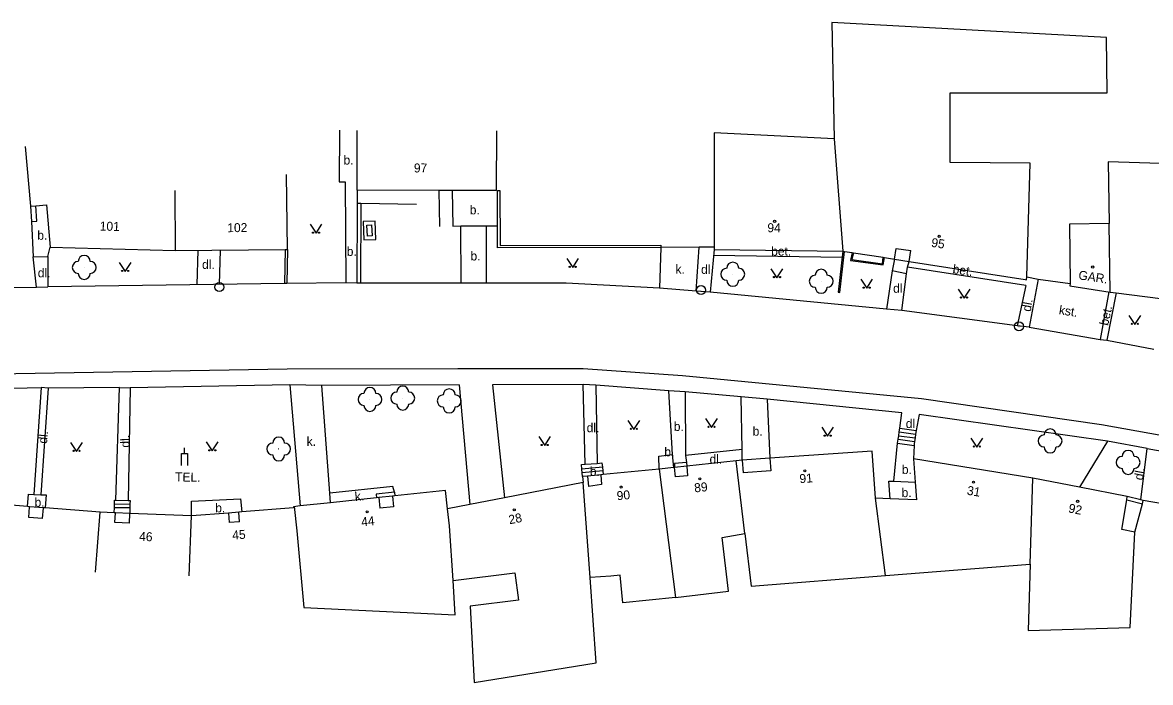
# Model space of a CAD drawing. Extents: x -582162 to -561283, y -1187583 to -1183539.
# Drawn here: x -571002.1 to -570907.8, y -1184952.9 to -1184897.8 of the extents above; entities that cross this region are included whole.
import ezdxf

# ---------------------------------------------------------------- set-up
doc = ezdxf.new("R2010")
doc.units = 0
for name, color, linetype in [('Vrstva 1', 7, 'Continuous'), ('Vrstva 10', 7, 'Continuous'), ('Vrstva 11', 7, 'Continuous'), ('Vrstva 14', 7, 'Continuous'), ('Vrstva 3', 7, 'Continuous'), ('Vrstva 4', 7, 'Continuous'), ('Vrstva 5', 7, 'Continuous'), ('Vrstva 6', 7, 'Continuous'), ('Vrstva 8', 7, 'Continuous'), ('Vrstva 9', 7, 'Continuous')]:
    doc.layers.add(name, color=color, linetype=linetype)

# ---------------------------------------------------------------- blocks, each defined once
blk = doc.blocks.new('1.079')
at = {"layer": 'Vrstva 1'}
for radius in [0.75, 0.001]:
    blk.add_circle((0, -0.001), radius, dxfattribs=at)
blk = doc.blocks.new('3.130')
at = {"layer": 'Vrstva 1'}
blk.add_circle((0, 0), 0.001, dxfattribs=at)
for centre, start, end in [((0, 1), 0, 180), ((-1, 0), 90, 270), ((1, 0), 270, 90), ((0, -1), 180, 360)]:
    blk.add_arc(centre, 1, start, end, dxfattribs=at)
blk = doc.blocks.new('3.140')
at = {"layer": 'Vrstva 1'}
blk.add_lwpolyline([(-1, 1.5), (0, 0), (1, 1.5)], dxfattribs=at)
for centre in [(-0.5, 0.1), (0.5, 0.1)]:
    blk.add_circle(centre, 0.1, dxfattribs=at)
blk = doc.blocks.new('4.020')
at = {"layer": 'Vrstva 1'}
blk.add_circle((0, 0), 0.175, dxfattribs=at)
blk = doc.blocks.new('4.120')
at = {"layer": 'Vrstva 1'}
blk.add_line((0, 2), (0, 3), dxfattribs=at)
blk.add_lwpolyline([(-0.5, 0), (-0.5, 2), (0.5, 2), (0.5, 0)], dxfattribs=at)

msp = doc.modelspace()

# ---------------------------------------------------------------- linework, layer by layer
at = {"layer": 'Vrstva 10'}
for points in [[(-570975.62, -1184906.76), (-570975.64, -1184911.07), (-570975.14, -1184911.07), (-570975.09, -1184919.5)], [(-570967.31, -1184911.79), (-570967.25, -1184914.79)], [(-570966.21, -1184911.79), (-570966.15, -1184914.77), (-570965.47, -1184914.73)], [(-570974.14, -1184912.84), (-570973.84, -1184912.84)], [(-570973.84, -1184912.84), (-570969.19, -1184912.92)], [(-571001.35, -1184914.38), (-571001.23, -1184917.32)], [(-570973.57, -1184915.91), (-570972.57, -1184915.87), (-570972.64, -1184914.35), (-570973.64, -1184914.39), (-570973.57, -1184915.91)], [(-570973.28, -1184915.6), (-570973.33, -1184914.67), (-570972.93, -1184914.66), (-570972.88, -1184915.58), (-570973.28, -1184915.6)], [(-570965.47, -1184914.73), (-570963.32, -1184914.75)], [(-570965.46, -1184919.53), (-570965.47, -1184914.73)], [(-570963.32, -1184914.75), (-570962.41, -1184914.74)], [(-570963.32, -1184919.53), (-570963.32, -1184914.75)], [(-570999.98, -1184917.3), (-570999.8, -1184916.52)], [(-570948.76, -1184916.56), (-570948.88, -1184919.95)], [(-570945.82, -1184920.19), (-570945.56, -1184916.53)], [(-571001.23, -1184917.32), (-570999.98, -1184917.3)], [(-571000.94, -1184919.85), (-571001.23, -1184917.32)], [(-570999.98, -1184917.3), (-570999.98, -1184919.84)], [(-570987.46, -1184916.78), (-570987.54, -1184919.67)], [(-570985.6, -1184916.77), (-570985.68, -1184919.65)], [(-570944.31, -1184916.72), (-570944.63, -1184920.29)], [(-570933.62, -1184917.38), (-570944.35, -1184917.21)], [(-570929.23, -1184917.52), (-570929.43, -1184918.5)], [(-570929.43, -1184918.5), (-570929.91, -1184921.69)], [(-570928.23, -1184918.74), (-570929.43, -1184918.5)], [(-570928.23, -1184918.74), (-570928.14, -1184918.19)], [(-570928.14, -1184918.19), (-570928.02, -1184917.71)], [(-570918.27, -1184919.73), (-570928.14, -1184918.19)], [(-570928.62, -1184921.81), (-570928.23, -1184918.74)], [(-570917.22, -1184919.2), (-570917.98, -1184923.19)], [(-571018.47, -1184919.98), (-571000.94, -1184919.85)], [(-571000.94, -1184919.85), (-570999.98, -1184919.84)], [(-570980.22, -1184919.57), (-570999.98, -1184919.84)], [(-570980.02, -1184919.57), (-570980.22, -1184919.57)], [(-570975.09, -1184919.5), (-570980.02, -1184919.57)], [(-570974.16, -1184919.54), (-570975.09, -1184919.5)], [(-570973.86, -1184919.54), (-570974.16, -1184919.54)], [(-570965.46, -1184919.53), (-570973.86, -1184919.54)], [(-570963.32, -1184919.53), (-570965.46, -1184919.53)], [(-570948.88, -1184919.95), (-570956.68, -1184919.53), (-570963.32, -1184919.53)], [(-570945.82, -1184920.19), (-570948.88, -1184919.95)], [(-570944.63, -1184920.29), (-570945.82, -1184920.19)], [(-570929.91, -1184921.69), (-570944.63, -1184920.29)], [(-570918.27, -1184919.73), (-570918.98, -1184923.08)], [(-570911.31, -1184920.25), (-570912.06, -1184924.23)], [(-570910.71, -1184920.34), (-570911.48, -1184924.29)], [(-570928.62, -1184921.81), (-570929.91, -1184921.69)], [(-570918.98, -1184923.08), (-570928.62, -1184921.81)], [(-570917.98, -1184923.19), (-570918.98, -1184923.08)], [(-570917.98, -1184923.19), (-570912.06, -1184924.23)], [(-570912.06, -1184924.23), (-570911.48, -1184924.29)], [(-570911.48, -1184924.29), (-570907.56, -1184925.03)], [(-571004.32, -1184927.09), (-570979.98, -1184926.69), (-570965.74, -1184926.67)], [(-570965.74, -1184926.67), (-570962.98, -1184926.67)], [(-570962.98, -1184926.67), (-570955.25, -1184926.66), (-570946.96, -1184927.24), (-570926.98, -1184929.16), (-570911.93, -1184931.33), (-570890.18, -1184935.24), (-570870.81, -1184939.01), (-570871.39, -1184940.27)], [(-571012.32, -1184928.52), (-571000.54, -1184928.25)], [(-571000.54, -1184928.25), (-571001.16, -1184937.17)], [(-570999.95, -1184928.29), (-571000.57, -1184937.2)], [(-570999.95, -1184928.29), (-571000.54, -1184928.25)], [(-570994.01, -1184928.24), (-570999.95, -1184928.29)], [(-570994.31, -1184937.66), (-570994.01, -1184928.24)], [(-570994.01, -1184928.24), (-570993.12, -1184928.27)], [(-570993.12, -1184928.27), (-570993.27, -1184937.68)], [(-570979.76, -1184928.03), (-570993.12, -1184928.27)], [(-570979.76, -1184928.03), (-570978.91, -1184938.14)], [(-570977.09, -1184928.07), (-570979.76, -1184928.03)], [(-570965.62, -1184928.03), (-570977.09, -1184928.07)], [(-570976.43, -1184937.06), (-570977.09, -1184928.07)], [(-570965.62, -1184928.03), (-570964.73, -1184938.01)], [(-570955.25, -1184928), (-570962.84, -1184928.02)], [(-570962.84, -1184928.02), (-570961.84, -1184937.46)], [(-570955.09, -1184934.65), (-570955.25, -1184928)], [(-570954.2, -1184928.06), (-570955.25, -1184928)], [(-570948.09, -1184928.51), (-570954.2, -1184928.06)], [(-570954.2, -1184928.06), (-570954.09, -1184934.58)], [(-570947.79, -1184933.84), (-570948.09, -1184928.51)], [(-570946.73, -1184928.61), (-570948.09, -1184928.51)], [(-570942.04, -1184929.01), (-570946.73, -1184928.61)], [(-570946.73, -1184928.61), (-570946.69, -1184933.92)], [(-570941.97, -1184933.42), (-570942.04, -1184929.01)], [(-570939.87, -1184929.22), (-570942.04, -1184929.01)], [(-570928.8, -1184931.65), (-570928.63, -1184930.35), (-570939.87, -1184929.22)], [(-570939.87, -1184929.22), (-570939.64, -1184934.16)], [(-570911.44, -1184932.74), (-570927.18, -1184930.5), (-570927.43, -1184931.84)], [(-570928.84, -1184931.96), (-570928.8, -1184931.65)], [(-570928.8, -1184931.65), (-570927.43, -1184931.84)], [(-570928.97, -1184932.89), (-570928.92, -1184932.57)], [(-570928.92, -1184932.57), (-570928.88, -1184932.27)], [(-570928.92, -1184932.57), (-570927.56, -1184932.76)], [(-570928.88, -1184932.27), (-570928.84, -1184931.96)], [(-570928.88, -1184932.27), (-570927.52, -1184932.45)], [(-570928.84, -1184931.96), (-570927.47, -1184932.14)], [(-570927.52, -1184932.45), (-570927.56, -1184932.76)], [(-570927.47, -1184932.14), (-570927.52, -1184932.45)], [(-570927.43, -1184931.84), (-570927.47, -1184932.14)], [(-570941.97, -1184933.42), (-570946.69, -1184933.92)], [(-570941.96, -1184934.32), (-570941.97, -1184933.42)], [(-570929.29, -1184936.08), (-570928.97, -1184932.89)], [(-570928.97, -1184932.89), (-570927.6, -1184933.08)], [(-570927.6, -1184933.08), (-570927.65, -1184934.19)], [(-570927.56, -1184932.76), (-570927.59, -1184932.94), (-570927.6, -1184933.08)], [(-570911.44, -1184932.74), (-570913.78, -1184936.57)], [(-570908.13, -1184933.33), (-570911.44, -1184932.74)], [(-570908.64, -1184937.63), (-570908.13, -1184933.33)], [(-570908.13, -1184933.33), (-570890.36, -1184936.5)], [(-570948.91, -1184935.06), (-570948.92, -1184933.97), (-570947.79, -1184933.84)], [(-570947.67, -1184934.93), (-570947.79, -1184933.84)], [(-570946.62, -1184934.5), (-570947.63, -1184934.6), (-570947.61, -1184934.92)], [(-570946.69, -1184933.92), (-570946.62, -1184934.5)], [(-570946.62, -1184934.5), (-570946.59, -1184934.81)], [(-570955.36, -1184935.06), (-570955.39, -1184934.67), (-570955.09, -1184934.65)], [(-570953.65, -1184934.89), (-570955.36, -1184935.06)], [(-570955.33, -1184935.37), (-570955.36, -1184935.06)], [(-570953.62, -1184935.21), (-570955.33, -1184935.37)], [(-570955.3, -1184935.69), (-570955.33, -1184935.37)], [(-570955.09, -1184934.65), (-570954.09, -1184934.58)], [(-570954.09, -1184934.58), (-570953.69, -1184934.55), (-570953.65, -1184934.89)], [(-570953.65, -1184934.89), (-570953.62, -1184935.21)], [(-570953.62, -1184935.21), (-570953.59, -1184935.52)], [(-570929.61, -1184937.55), (-570929.72, -1184936.06), (-570929.29, -1184936.08)], [(-570929.29, -1184936.08), (-570927.51, -1184936.15)], [(-571001.68, -1184938.19), (-571001.6, -1184937.14), (-571001.16, -1184937.17)], [(-571001.16, -1184937.17), (-571000.57, -1184937.2)], [(-571000.57, -1184937.2), (-571000.13, -1184937.22), (-571000.22, -1184938.3)], [(-570971.03, -1184937), (-570971.15, -1184936.5), (-570976.43, -1184937.06)], [(-570976.37, -1184937.87), (-570976.43, -1184937.06)], [(-570971.03, -1184937), (-570972.56, -1184937.16), (-570972.53, -1184937.46)], [(-570971.03, -1184937), (-570971, -1184937.3)], [(-570908.64, -1184937.63), (-570909.78, -1184937.34)], [(-570994.45, -1184938.72), (-570994.43, -1184938.26)], [(-570994.43, -1184938.26), (-570994.42, -1184937.96)], [(-570994.43, -1184938.26), (-570993.13, -1184938.28)], [(-570994.42, -1184937.96), (-570994.41, -1184937.66), (-570994.31, -1184937.66)], [(-570994.42, -1184937.96), (-570993.13, -1184937.98)], [(-570994.31, -1184937.66), (-570993.27, -1184937.68)], [(-570993.27, -1184937.68), (-570993.12, -1184937.68), (-570993.13, -1184937.98)], [(-570993.13, -1184938.28), (-570993.14, -1184938.77)], [(-570993.13, -1184937.98), (-570993.13, -1184938.28)], [(-570987.98, -1184938.97), (-570987.98, -1184937.73), (-570983.88, -1184937.54), (-570983.79, -1184938.64)], [(-570909.83, -1184937.64), (-570908.52, -1184937.97)], [(-570908.44, -1184937.68), (-570908.64, -1184937.63)]]:
    msp.add_lwpolyline(points, dxfattribs=at)
at = {"layer": 'Vrstva 4'}
for points in [[(-570974.15, -1184911.77), (-570974.14, -1184906.77)], [(-570962.5, -1184906.8), (-570962.52, -1184911.8), (-570966.21, -1184911.79)], [(-571001.88, -1184908.12), (-571001.44, -1184913.1)], [(-570979.97, -1184916.73), (-570980.04, -1184910.44)], [(-570989.37, -1184911.8), (-570989.34, -1184916.8)], [(-570967.31, -1184911.79), (-570974.15, -1184911.77)], [(-570966.21, -1184911.79), (-570967.31, -1184911.79)], [(-571001.44, -1184913.1), (-571000.99, -1184913.06)], [(-571000.99, -1184913.06), (-571000.09, -1184912.98), (-570999.8, -1184916.52)], [(-570999.8, -1184916.52), (-570989.34, -1184916.8)], [(-570944.31, -1184916.52), (-570944.31, -1184916.72)], [(-570929.23, -1184917.52), (-570929.1, -1184916.62)], [(-570989.34, -1184916.8), (-570980.17, -1184916.73)], [(-570980.17, -1184916.73), (-570979.97, -1184916.73)], [(-570944.31, -1184916.72), (-570933.56, -1184916.85)], [(-570933.56, -1184916.85), (-570933.41, -1184916.87)], [(-570933.41, -1184916.87), (-570932.77, -1184916.97)], [(-570932.77, -1184916.97), (-570932.67, -1184916.99)], [(-570932.67, -1184916.99), (-570930.17, -1184917.37)], [(-570930.17, -1184917.37), (-570930.07, -1184917.39)], [(-570930.07, -1184917.39), (-570929.23, -1184917.52)], [(-570929.23, -1184917.52), (-570928.02, -1184917.71)], [(-570928.02, -1184917.71), (-570927.88, -1184916.8)], [(-570928.02, -1184917.71), (-570918.31, -1184919.23)], [(-570918.31, -1184919.23), (-570918.21, -1184919.25)], [(-570918.21, -1184919.25), (-570918.17, -1184918.99)], [(-570914.56, -1184919.56), (-570914.59, -1184919.76)], [(-570914.59, -1184919.76), (-570914.04, -1184919.84)], [(-570914.04, -1184919.84), (-570911.74, -1184920.19)], [(-570911.74, -1184920.19), (-570911.2, -1184920.27)], [(-570911.2, -1184920.27), (-570910.71, -1184920.34)], [(-570910.71, -1184920.34), (-570907.01, -1184920.8), (-570905.97, -1184920.94), (-570898.31, -1184921.91)], [(-570930.81, -1184937.5), (-570931.09, -1184933.55), (-570939.64, -1184934.16)], [(-570942.46, -1184934.36), (-570946.59, -1184934.81)], [(-570941.96, -1184934.32), (-570942.46, -1184934.36)], [(-570939.64, -1184934.16), (-570941.96, -1184934.32)], [(-570941.96, -1184934.32), (-570941.88, -1184935.37)], [(-570939.64, -1184934.16), (-570939.56, -1184935.2)], [(-570927.65, -1184934.19), (-570927.51, -1184936.15)], [(-570917.68, -1184935.81), (-570927.65, -1184934.19)], [(-570948.91, -1184935.06), (-570953.59, -1184935.52)], [(-570947.67, -1184934.93), (-570948.91, -1184935.06)], [(-570947.61, -1184934.92), (-570947.67, -1184934.93)], [(-570946.59, -1184934.81), (-570947.61, -1184934.92)], [(-570947.54, -1184935.7), (-570947.61, -1184934.92)], [(-570946.59, -1184934.81), (-570946.52, -1184935.61)], [(-570955.25, -1184936.19), (-570961.84, -1184937.46)], [(-570954.89, -1184935.65), (-570955.3, -1184935.69)], [(-570955.3, -1184935.69), (-570955.25, -1184936.19)], [(-570953.79, -1184935.54), (-570954.89, -1184935.65)], [(-570954.89, -1184935.65), (-570954.81, -1184936.5)], [(-570953.59, -1184935.52), (-570953.79, -1184935.54)], [(-570953.79, -1184935.54), (-570953.71, -1184936.36)], [(-570927.51, -1184936.15), (-570927.4, -1184937.64), (-570929.61, -1184937.55)], [(-570913.78, -1184936.57), (-570917.68, -1184935.81)], [(-570971.2, -1184937.32), (-570972.33, -1184937.44)], [(-570971, -1184937.3), (-570971.2, -1184937.32)], [(-570971.2, -1184937.32), (-570971.11, -1184938.21)], [(-570966.59, -1184938.37), (-570966.75, -1184936.84), (-570971, -1184937.3)], [(-570909.78, -1184937.34), (-570913.78, -1184936.57)], [(-570909.83, -1184937.64), (-570909.78, -1184937.34)], [(-571001.68, -1184938.19), (-571005.76, -1184937.85)], [(-571001.51, -1184938.2), (-571001.68, -1184938.19)], [(-571001.58, -1184939.11), (-571001.51, -1184938.2)], [(-571000.36, -1184938.29), (-571001.51, -1184938.2)], [(-571000.43, -1184939.19), (-571000.36, -1184938.29)], [(-571000.22, -1184938.3), (-571000.36, -1184938.29)], [(-570995.61, -1184938.67), (-571000.22, -1184938.3)], [(-570979.45, -1184938.3), (-570983.79, -1184938.64)], [(-570978.91, -1184938.14), (-570979.46, -1184938.2), (-570979.45, -1184938.3)], [(-570976.37, -1184937.87), (-570978.91, -1184938.14)], [(-570972.53, -1184937.46), (-570976.37, -1184937.87)], [(-570972.33, -1184937.44), (-570972.53, -1184937.46)], [(-570972.33, -1184937.44), (-570972.24, -1184938.33)], [(-570964.73, -1184938.01), (-570966.59, -1184938.37)], [(-570961.84, -1184937.46), (-570964.73, -1184938.01)], [(-570929.61, -1184937.55), (-570930.81, -1184937.5)], [(-570909.14, -1184940.33), (-570910.23, -1184940.1), (-570909.83, -1184937.64)], [(-570996.02, -1184943.66), (-570995.61, -1184938.67)], [(-570994.45, -1184938.72), (-570995.61, -1184938.67)], [(-570994.34, -1184938.72), (-570994.45, -1184938.72)], [(-570994.38, -1184939.52), (-570994.34, -1184938.72)], [(-570993.14, -1184938.77), (-570994.34, -1184938.72)], [(-570993.18, -1184939.57), (-570993.14, -1184938.77)], [(-570987.98, -1184938.97), (-570993.14, -1184938.77)], [(-570988.18, -1184943.97), (-570987.98, -1184938.97)], [(-570984.9, -1184938.73), (-570987.98, -1184938.97)], [(-570984.04, -1184938.66), (-570984.9, -1184938.73)], [(-570984.9, -1184938.73), (-570984.83, -1184939.53)], [(-570983.79, -1184938.64), (-570984.04, -1184938.66)], [(-570983.98, -1184939.46), (-570984.04, -1184938.66)]]:
    msp.add_lwpolyline(points, dxfattribs=at)
at = {"layer": 'Vrstva 5'}
for points in [[(-570934.47, -1184897.76), (-570934.29, -1184907.48)], [(-570911.53, -1184899.01), (-570934.47, -1184897.76)], [(-570911.46, -1184903.64), (-570911.53, -1184899.01)], [(-570924.58, -1184903.64), (-570911.46, -1184903.64)], [(-570924.58, -1184909.44), (-570924.58, -1184903.64)], [(-570944.3, -1184906.97), (-570944.31, -1184913.82)], [(-570934.29, -1184907.48), (-570944.3, -1184906.97)], [(-570934.29, -1184907.48), (-570933.56, -1184916.85)], [(-570917.9, -1184909.5), (-570924.58, -1184909.44)], [(-570918.17, -1184918.99), (-570917.9, -1184909.5)], [(-570911.37, -1184909.38), (-570911.29, -1184914.55)], [(-570898.31, -1184909.81), (-570911.37, -1184909.38)], [(-570944.31, -1184913.82), (-570944.31, -1184916.52)], [(-570911.29, -1184914.55), (-570914.61, -1184914.6)], [(-570914.61, -1184914.6), (-570914.56, -1184919.56)], [(-570911.2, -1184920.27), (-570911.29, -1184914.55)], [(-570941.74, -1184940.45), (-570942.46, -1184934.36)], [(-570948.91, -1184935.06), (-570947.53, -1184945.78)], [(-570954.68, -1184944.12), (-570955.25, -1184936.19)], [(-570917.9, -1184943), (-570917.68, -1184935.81)], [(-570979.41, -1184938.19), (-570979.18, -1184940.23)], [(-570929.98, -1184943.95), (-570930.81, -1184937.5)], [(-570966.42, -1184939.79), (-570966.59, -1184938.37)], [(-570966.11, -1184944.36), (-570966.42, -1184939.79)], [(-570979.18, -1184940.23), (-570978.59, -1184946.61)], [(-570943.64, -1184940.77), (-570941.74, -1184940.45)], [(-570943.1, -1184945.25), (-570943.64, -1184940.77)], [(-570941.74, -1184940.45), (-570941.22, -1184944.84)], [(-570909.53, -1184948.29), (-570909.14, -1184940.33)], [(-570929.98, -1184943.95), (-570917.9, -1184943)], [(-570917.9, -1184943), (-570918.06, -1184948.55)], [(-570966.11, -1184944.36), (-570960.95, -1184943.73)], [(-570960.95, -1184943.73), (-570960.67, -1184946.02)], [(-570952.17, -1184943.92), (-570952.93, -1184944)], [(-570951.94, -1184946.23), (-570952.17, -1184943.92)], [(-570941.22, -1184944.84), (-570929.98, -1184943.95)], [(-570965.95, -1184947.22), (-570966.11, -1184944.36)], [(-570952.93, -1184944), (-570954.68, -1184944.12)], [(-570954.17, -1184951.24), (-570954.68, -1184944.12)], [(-570947.53, -1184945.78), (-570951.94, -1184946.23)], [(-570947.53, -1184945.78), (-570943.1, -1184945.25)], [(-570978.59, -1184946.61), (-570965.95, -1184947.22)], [(-570960.67, -1184946.02), (-570964.7, -1184946.52)], [(-570964.7, -1184946.52), (-570964.36, -1184952.88)], [(-570918.06, -1184948.55), (-570909.53, -1184948.29)], [(-570964.36, -1184952.88), (-570954.17, -1184951.24)]]:
    msp.add_lwpolyline(points, dxfattribs=at)
at = {"layer": 'Vrstva 9'}
for points in [[(-570974.15, -1184911.77), (-570974.14, -1184912.84)], [(-570962.41, -1184914.74), (-570962.42, -1184911.8), (-570962.22, -1184911.8), (-570962.2, -1184916.37), (-570948.76, -1184916.36), (-570948.76, -1184916.56)], [(-570974.14, -1184912.84), (-570974.16, -1184919.54)], [(-570973.84, -1184912.84), (-570973.86, -1184919.54)], [(-571001.44, -1184913.1), (-571001.35, -1184914.38)], [(-571001.35, -1184914.38), (-571000.9, -1184914.35), (-571000.99, -1184913.06)], [(-570948.76, -1184916.56), (-570962.4, -1184916.57), (-570962.41, -1184914.74)], [(-570945.56, -1184916.53), (-570948.76, -1184916.56)], [(-570944.31, -1184916.52), (-570945.56, -1184916.53)], [(-570929.1, -1184916.62), (-570927.88, -1184916.8)], [(-570980.17, -1184916.73), (-570980.22, -1184919.57)], [(-570979.97, -1184916.73), (-570980.02, -1184919.57)], [(-570933.56, -1184916.85), (-570933.95, -1184920.29), (-570933.8, -1184920.31), (-570933.41, -1184916.87)], [(-570932.77, -1184916.97), (-570932.91, -1184917.63), (-570930.17, -1184918.01), (-570930.07, -1184917.39)], [(-570932.67, -1184916.99), (-570932.79, -1184917.54), (-570930.25, -1184917.9), (-570930.17, -1184917.37)], [(-570918.17, -1184918.99), (-570917.22, -1184919.2)], [(-570917.22, -1184919.2), (-570914.56, -1184919.56)], [(-570939.56, -1184935.2), (-570941.88, -1184935.37)], [(-570953.71, -1184936.36), (-570954.81, -1184936.5)], [(-570946.52, -1184935.61), (-570947.54, -1184935.7)], [(-570971.11, -1184938.21), (-570972.24, -1184938.33)], [(-570909.14, -1184940.33), (-570908.52, -1184937.97)], [(-570908.52, -1184937.97), (-570908.44, -1184937.68)], [(-570895.51, -1184939.92), (-570908.44, -1184937.68)], [(-571000.43, -1184939.19), (-571001.58, -1184939.11)], [(-570993.18, -1184939.57), (-570994.38, -1184939.52)], [(-570983.98, -1184939.46), (-570984.83, -1184939.53)]]:
    msp.add_lwpolyline(points, dxfattribs=at)

# ---------------------------------------------------------------- block references
at = {"layer": 'Vrstva 1', "xscale": 0.5, "yscale": 0.5, "rotation": 90}
for p in [(-570985.66, -1184919.86), (-570945.4, -1184920.11)]:
    msp.add_blockref('1.079', p, dxfattribs=at)
at = {"layer": 'Vrstva 1', "xscale": 0.5, "yscale": 0.5}
msp.add_blockref('1.079', (-570918.83, -1184923.14), dxfattribs=at)
at = {"layer": 'Vrstva 11', "xscale": 0.5, "yscale": 0.5}
for p in [(-570996.95, -1184918.21), (-570942.75, -1184918.78), (-570935.36, -1184919.37), (-570973.07, -1184929.24), (-570970.33, -1184929.13), (-570966.45, -1184929.36), (-570916.23, -1184932.71), (-570980.7, -1184933.38), (-570909.71, -1184934.5)]:
    msp.add_blockref('3.130', p, dxfattribs=at)
at = {"layer": 'Vrstva 3', "xscale": 0.5, "yscale": 0.5}
for p in [(-570977.58, -1184915.36), (-570956.13, -1184918.22), (-570993.53, -1184918.56), (-570939.06, -1184919.07), (-570931.56, -1184919.95), (-570923.42, -1184920.78), (-570909.15, -1184922.97), (-570951.02, -1184931.74), (-570944.53, -1184931.58), (-570934.82, -1184932.32), (-570958.47, -1184933.1), (-570922.35, -1184933.22), (-570997.59, -1184933.59), (-570986.25, -1184933.54)]:
    msp.add_blockref('3.140', p, dxfattribs=at)
at = {"layer": 'Vrstva 8', "xscale": 0.5, "yscale": 0.5}
for p in [(-570939.25, -1184914.36), (-570925.5, -1184915.62), (-570912.67, -1184918.18), (-570936.73, -1184935.2), (-570945.51, -1184935.88), (-570922.63, -1184936.15), (-570952.08, -1184936.56), (-570913.93, -1184937.75), (-570973.3, -1184938.63), (-570961.01, -1184938.46)]:
    msp.add_blockref('4.020', p, dxfattribs=at)
at = {"layer": 'Vrstva 9', "xscale": 0.5, "yscale": 0.5}
msp.add_blockref('4.120', (-570988.57, -1184934.77), dxfattribs=at)

# ---------------------------------------------------------------- texts
at = {"layer": 'Vrstva 14'}
for s, p in [('b.', (-570975.28, -1184909.62)), ('b.', (-570964.73, -1184913.78)), ('b.', (-571000.87, -1184915.9)), ('b.', (-570975.01, -1184917.25)), ('b.', (-570964.67, -1184917.63)), ('dl.', (-571000.83, -1184919.04)), ('k.', (-570947.54, -1184918.73)), ('dl.', (-570945.4, -1184918.75)), ('dl.', (-570929.35, -1184920.33)), ('dl.', (-570954.96, -1184931.98)), ('b.', (-570947.68, -1184931.87)), ('b.', (-570941.09, -1184932.27)), ('dl.', (-570928.29, -1184931.63)), ('k.', (-570978.36, -1184933.12)), ('b.', (-570948.47, -1184933.99)), ('dl.', (-570944.69, -1184934.6)), ('b.', (-570954.7, -1184935.63)), ('b.', (-570928.62, -1184935.47)), ('b.', (-570928.64, -1184937.4)), ('b.', (-571001.1, -1184938.2)), ('b.', (-570986, -1184938.67))]:
    msp.add_text(s, height=0.75, dxfattribs=at).set_placement(p)
for s, rotation, p in [('bet.', 0.149, (-570939.54, -1184917.23)), ('dl.', 0.149, (-570987.1, -1184918.34)), ('bet.', 351.425, (-570924.41, -1184918.69)), ('GAR.', 351.437, (-570913.9, -1184919.2)), ('dl.', 79.939, (-570917.86, -1184921.95)), ('kst.', 351.27, (-570915.53, -1184922.11)), ('bet.', 77.315, (-570911.39, -1184923.12)), ('dl.', 84.442, (-571000.07, -1184932.96)), ('dl.', 91.142, (-570993.16, -1184933.26)), ('TEL.', 358.852, (-570989.36, -1184936.08)), ('dl.', 79.472, (-570908.5, -1184936.03)), ('k.', 6.034, (-570974.3, -1184937.73))]:
    msp.add_text(s, height=0.75, rotation=rotation, dxfattribs=at).set_placement(p)
at = {"layer": 'Vrstva 6'}
for s, rotation, p in [('97', 359.838, (-570969.4, -1184910.28)), ('101', 358.479, (-570995.66, -1184915.13)), ('102', 0.41, (-570984.99, -1184915.27)), ('94', 359.313, (-570939.86, -1184915.27)), ('95', 351.102, (-570926.2, -1184916.48)), ('91', 4.101, (-570937.15, -1184936.24)), ('89', 6.042, (-570945.93, -1184937.01)), ('90', 5.636, (-570952.41, -1184937.67)), ('31', 350.768, (-570923.22, -1184937.19)), ('92', 349.056, (-570914.74, -1184938.67)), ('44', 6.081, (-570973.76, -1184939.85)), ('28', 10.855, (-570961.41, -1184939.67)), ('45', 4.542, (-570984.55, -1184940.96)), ('46', 357.726, (-570992.37, -1184941.05))]:
    msp.add_text(s, height=0.75, rotation=rotation, dxfattribs=at).set_placement(p)

doc.saveas('drawing.dxf')
